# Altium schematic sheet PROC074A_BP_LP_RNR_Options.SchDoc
size 431 x 279 mm; Date: Not shown in title block; ApprovedBy: Not shown in title block; CheckedBy: Not shown in title block; Author: Not shown in title block; CompanyName: Not shown in title block; Engineer: Not shown in title block; Organization: Not shown in title block; Address1: Not shown in title block; Address2: Not shown in title block; Address3: Not shown in title block; Address4: Not shown in title block; DocumentNumber: 1; Revision: Use project parameter SCH_Rev; SheetNumber: 9; SheetTotal: 22; PageSetup: Record=PageOptions¦CenterHorizontal=True¦CenterVertical=True¦PrintScale=1.00¦XCorrection=1.00¦YCorrection=1.00¦PrintKind=0¦BorderSize=5000000¦LeftOffset=0¦BottomOffset=0¦Orientation=2¦PaperLength=1000¦PaperWidth=1000¦Scale=100¦PaperSource=15¦PrintQuality=600¦MediaType=1¦DitherType=10¦PaperKind=Letter¦PrintScaleMode=1
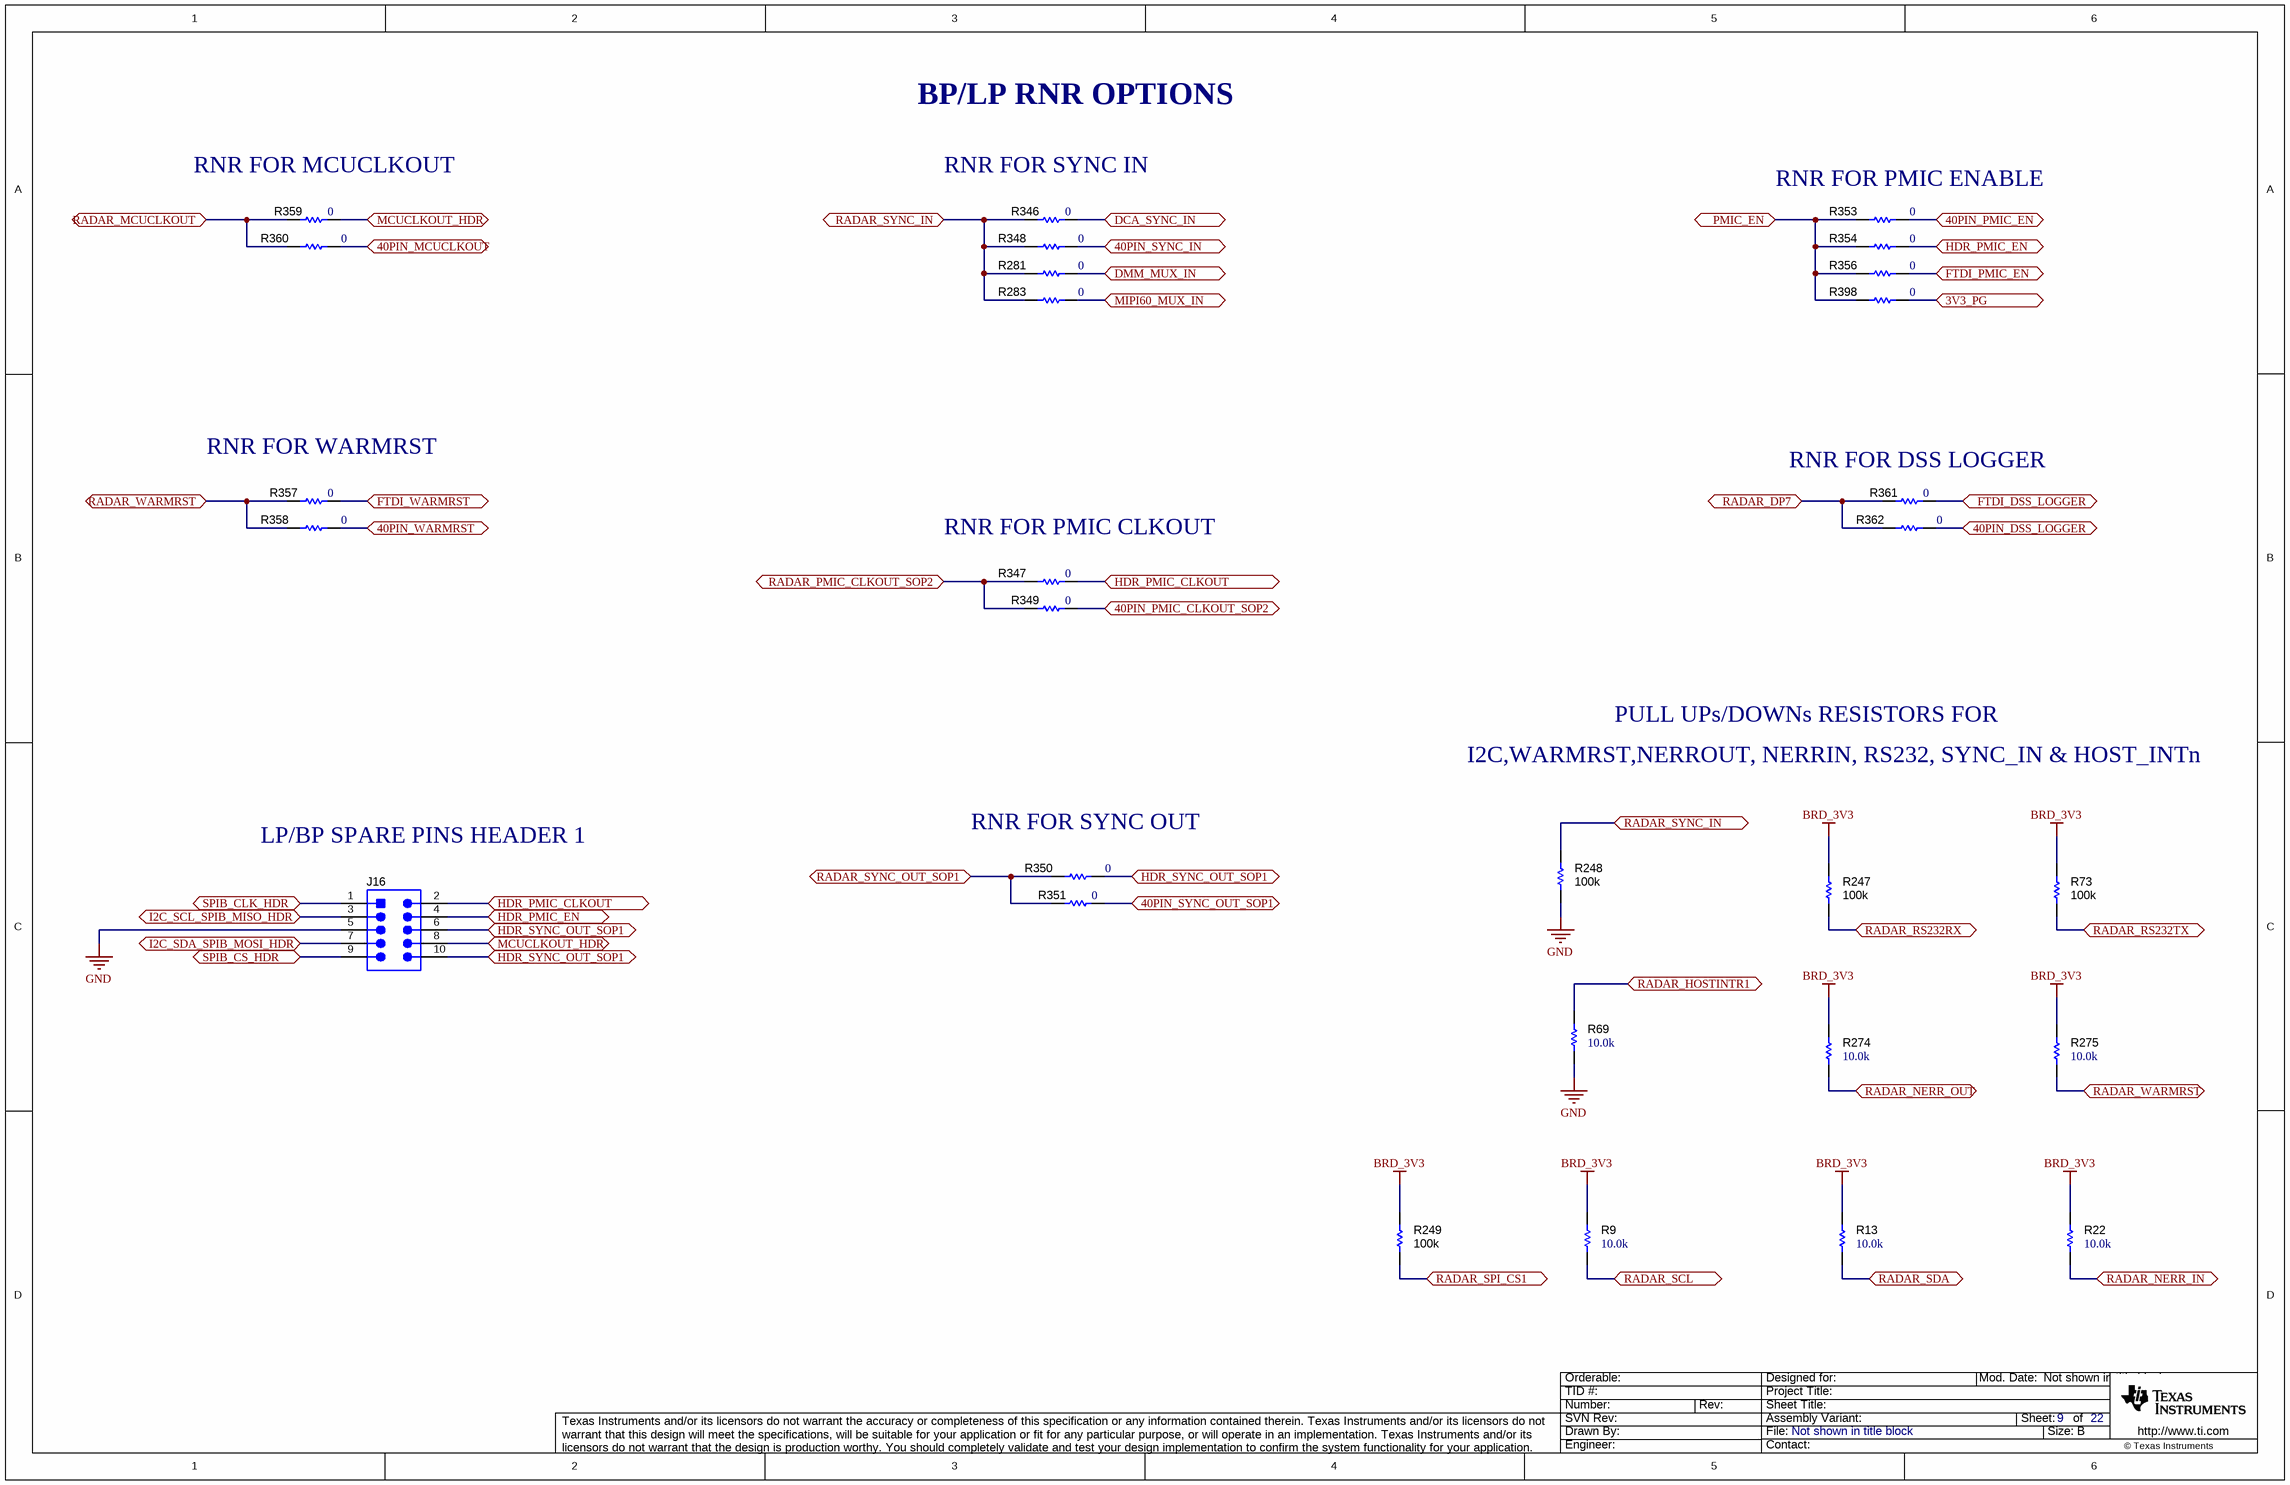
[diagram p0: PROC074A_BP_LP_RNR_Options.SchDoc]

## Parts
J16  TSW-105-07-G-D  [TSW-105-07-G-D]  (value not drawn)
R9  ValueDisplayed: 10.0k  [0402]  (hidden comment: CRCW040210K0FKED)
R13  ValueDisplayed: 10.0k  [0402]  (hidden comment: CRCW040210K0FKED)
R22  ValueDisplayed: 10.0k  [0402]  (hidden comment: CRCW040210K0FKED)
R69  ValueDisplayed: 10.0k  [0402]  (hidden comment: CRCW040210K0FKED)
R73  ValueDisplayed: 100k  [0402L]  (hidden comment: CRCW0402100KFKED)
R247  ValueDisplayed: 100k  [0402L]  (hidden comment: CRCW0402100KFKED)
R248  ValueDisplayed: 100k  [0402L]  (hidden comment: CRCW0402100KFKED)
R249  ValueDisplayed: 100k  [0402L]  (hidden comment: CRCW0402100KFKED)
R274  ValueDisplayed: 10.0k  [0402]  (hidden comment: CRCW040210K0FKED)
R275  ValueDisplayed: 10.0k  [0402]  (hidden comment: CRCW040210K0FKED)
R281  ValueDisplayed: 0  [0402]  (hidden comment: ERJ-2GE0R00X)
R283  ValueDisplayed: 0  [0402]  (hidden comment: ERJ-2GE0R00X)
R346  ValueDisplayed: 0  [0402]  (hidden comment: ERJ-2GE0R00X)
R347  ValueDisplayed: 0  [0402]  (hidden comment: ERJ-2GE0R00X)
R348  ValueDisplayed: 0  [0402]  (hidden comment: ERJ-2GE0R00X)
R349  ValueDisplayed: 0  [0402]  (hidden comment: ERJ-2GE0R00X)
R350  ValueDisplayed: 0  [0402]  (hidden comment: ERJ-2GE0R00X)
R351  ValueDisplayed: 0  [0402]  (hidden comment: ERJ-2GE0R00X)
R353  ValueDisplayed: 0  [0402]  (hidden comment: ERJ-2GE0R00X)
R354  ValueDisplayed: 0  [0402]  (hidden comment: ERJ-2GE0R00X)
R356  ValueDisplayed: 0  [0402]  (hidden comment: ERJ-2GE0R00X)
R357  ValueDisplayed: 0  [0402]  (hidden comment: ERJ-2GE0R00X)
R358  ValueDisplayed: 0  [0402]  (hidden comment: ERJ-2GE0R00X)
R359  ValueDisplayed: 0  [0402]  (hidden comment: ERJ-2GE0R00X)
R360  ValueDisplayed: 0  [0402]  (hidden comment: ERJ-2GE0R00X)
R361  ValueDisplayed: 0  [0402]  (hidden comment: ERJ-2GE0R00X)
R362  ValueDisplayed: 0  [0402]  (hidden comment: ERJ-2GE0R00X)
R398  ValueDisplayed: 0  [0402]  (hidden comment: ERJ-2GE0R00X)

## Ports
3V3_PG, 40PIN_DSS_LOGGER, 40PIN_MCUCLKOUT, 40PIN_PMIC_CLKOUT_SOP2, 40PIN_PMIC_EN, 40PIN_SYNC_IN, 40PIN_SYNC_OUT_SOP1, 40PIN_WARMRST, DCA_SYNC_IN, DMM_MUX_IN, FTDI_DSS_LOGGER, FTDI_PMIC_EN, FTDI_WARMRST, HDR_PMIC_CLKOUT, HDR_PMIC_EN, HDR_SYNC_OUT_SOP1, I2C_SCL_SPIB_MISO_HDR, I2C_SDA_SPIB_MOSI_HDR, MCUCLKOUT_HDR, MIPI60_MUX_IN, PMIC_EN, RADAR_DP7, RADAR_HOSTINTR1, RADAR_MCUCLKOUT, RADAR_NERR_IN, RADAR_NERR_OUT, RADAR_PMIC_CLKOUT_SOP2, RADAR_RS232RX, RADAR_RS232TX, RADAR_SCL, RADAR_SDA, RADAR_SPI_CS1, RADAR_SYNC_IN, RADAR_SYNC_OUT_SOP1, RADAR_WARMRST, SPIB_CLK_HDR, SPIB_CS_HDR

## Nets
BRD_3V3: R9.2 R13.2 R22.2 R73.2 R247.2 R249.2 R274.2 R275.2
GND: J16.5 R69.1 R248.1
3V3_PG: R398.2 ; port 3V3_PG
40PIN_DSS_LOGGER: R362.2 ; port 40PIN_DSS_LOGGER
40PIN_MCUCLKOUT: R360.2 ; port 40PIN_MCUCLKOUT
40PIN_PMIC_CLKOUT_SOP2: R349.2 ; port 40PIN_PMIC_CLKOUT_SOP2
40PIN_PMIC_EN: R353.2 ; port 40PIN_PMIC_EN
40PIN_SYNC_IN: R348.2 ; port 40PIN_SYNC_IN
40PIN_SYNC_OUT_SOP1: R351.2 ; port 40PIN_SYNC_OUT_SOP1
40PIN_WARMRST: R358.2 ; port 40PIN_WARMRST
DCA_SYNC_IN: R346.2 ; port DCA_SYNC_IN
DMM_MUX_IN: R281.2 ; port DMM_MUX_IN
FTDI_DSS_LOGGER: R361.2 ; port FTDI_DSS_LOGGER
FTDI_PMIC_EN: R356.2 ; port FTDI_PMIC_EN
FTDI_WARMRST: R357.2 ; port FTDI_WARMRST
HDR_PMIC_CLKOUT: J16.2 R347.2 ; port HDR_PMIC_CLKOUT
HDR_PMIC_EN: J16.4 R354.2 ; port HDR_PMIC_EN
HDR_SYNC_OUT_SOP1: J16.6 J16.10 R350.2 ; port HDR_SYNC_OUT_SOP1
I2C_SCL_SPIB_MISO_HDR: J16.3 ; port I2C_SCL_SPIB_MISO_HDR
I2C_SDA_SPIB_MOSI_HDR: J16.7 ; port I2C_SDA_SPIB_MOSI_HDR
MCUCLKOUT_HDR: J16.8 R359.2 ; port MCUCLKOUT_HDR
MIPI60_MUX_IN: R283.2 ; port MIPI60_MUX_IN
PMIC_EN: R353.1 R354.1 R356.1 R398.1 ; port PMIC_EN
RADAR_DP7: R361.1 R362.1 ; port RADAR_DP7
RADAR_HOSTINTR1: R69.2 ; port RADAR_HOSTINTR1
RADAR_MCUCLKOUT: R359.1 R360.1 ; port RADAR_MCUCLKOUT
RADAR_NERR_IN: R22.1 ; port RADAR_NERR_IN
RADAR_NERR_OUT: R274.1 ; port RADAR_NERR_OUT
RADAR_PMIC_CLKOUT_SOP2: R347.1 R349.1 ; port RADAR_PMIC_CLKOUT_SOP2
RADAR_RS232RX: R247.1 ; port RADAR_RS232RX
RADAR_RS232TX: R73.1 ; port RADAR_RS232TX
RADAR_SCL: R9.1 ; port RADAR_SCL
RADAR_SDA: R13.1 ; port RADAR_SDA
RADAR_SPI_CS1: R249.1 ; port RADAR_SPI_CS1
RADAR_SYNC_IN: R248.2 R281.1 R283.1 R346.1 R348.1 ; port RADAR_SYNC_IN
RADAR_SYNC_OUT_SOP1: R350.1 R351.1 ; port RADAR_SYNC_OUT_SOP1
RADAR_WARMRST: R275.1 R357.1 R358.1 ; port RADAR_WARMRST
SPIB_CLK_HDR: J16.1 ; port SPIB_CLK_HDR
SPIB_CS_HDR: J16.9 ; port SPIB_CS_HDR

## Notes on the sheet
- BP/LP RNR OPTIONS
- (near R359) RNR FOR MCUCLKOUT
- (near R346) RNR FOR SYNC IN
- (near R353) RNR FOR PMIC ENABLE
- (near R357) RNR FOR WARMRST
- (near R361) RNR FOR DSS LOGGER
- (near R347) RNR FOR PMIC CLKOUT
- I2C,WARMRST,NERROUT, NERRIN, RS232, SYNC_IN & HOST_INTn
- PULL UPs/DOWNs RESISTORS FOR
- (near R350) RNR FOR SYNC OUT
- LP/BP SPARE PINS HEADER 1

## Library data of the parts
J16 = CMP-0075410-2: Header, 100mil, 5x2, Gold, TH; Manufacturer: Samtec; Pitch_mm: 2.54; Cert_VDE: N; Gender: Male; Cert_CSA: Y; Voltage_V: 550V; Green_REACh: Passed; Current_A: 6.3A; Green_Lifecycle: Active; Row_Count: 2
R9 R13 R22 R69 R274 R275 = CMP-0025958-3: RES, 10.0 k, 1%, 0.063 W, AEC-Q200 Grade 0, 0402; Manufacturer: Vishay-Dale; Power_W: 63mW; TempCo: 100 ppm/C; Value_Code: 10k0; Value: 10.0k; EIA_Code: E96; Res_ohm: 10k; SizeX_mm: 1; SizeY_mm: 0.5; SizeZ_mm: 0.6; Value2: 0.063W; CompType: Resistor; AEC Qualified: Y; VDC_V: 50V; AEC Category: Q200; AEC Grade: 0; INSTALLATION: DNP
R73 R247-R249 = CMP-0025950-2: RES, 100 k, 1%, 0.063 W, 0402; Manufacturer: Vishay-Dale; Power_W: 63mW; TempCo: 100 ppm/C; U/M: EA; Value: 100k; EIA_Code: E96; SizeX_mm: 1; SizeY_mm: 0.5; SizeZ_mm: 0.6; Value2: 0.063W; CompType: Resistor; VDC_V: 50V; AEC Category: Q200; INSTALLATION: DNP
R281 R283 R347 R348 R350 R353 R354 R356 R358 R360 R362 = CMP-0026992-3: RES, 0, 5%, 0.1 W, AEC-Q200 Grade 0, 0402; Manufacturer: Panasonic; Power_W: 100mW; TempCo: 600 ppm/C; Value_Code: 0000; Value: 0; EIA_Code: E24; SizeX_mm: 1; SizeY_mm: 0.5; SizeZ_mm: 0.6; Value2: 0.1W; CompType: Resistor; AEC Qualified: Y; VDC_V: 50V; AEC Category: Q200; SizeAreaWB_mm2: 3; INSTALLATION: DNP
R346 R349 R351 R357 R359 R361 R398 = CMP-0026992-3: RES, 0, 5%, 0.1 W, AEC-Q200 Grade 0, 0402; Manufacturer: Panasonic; Power_W: 100mW; TempCo: 600 ppm/C; Value_Code: 0000; Value: 0; EIA_Code: E24; SizeX_mm: 1; SizeY_mm: 0.5; SizeZ_mm: 0.6; Value2: 0.1W; AEC Qualified: Y; VDC_V: 50V; AEC Category: Q200; SizeAreaWB_mm2: 3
